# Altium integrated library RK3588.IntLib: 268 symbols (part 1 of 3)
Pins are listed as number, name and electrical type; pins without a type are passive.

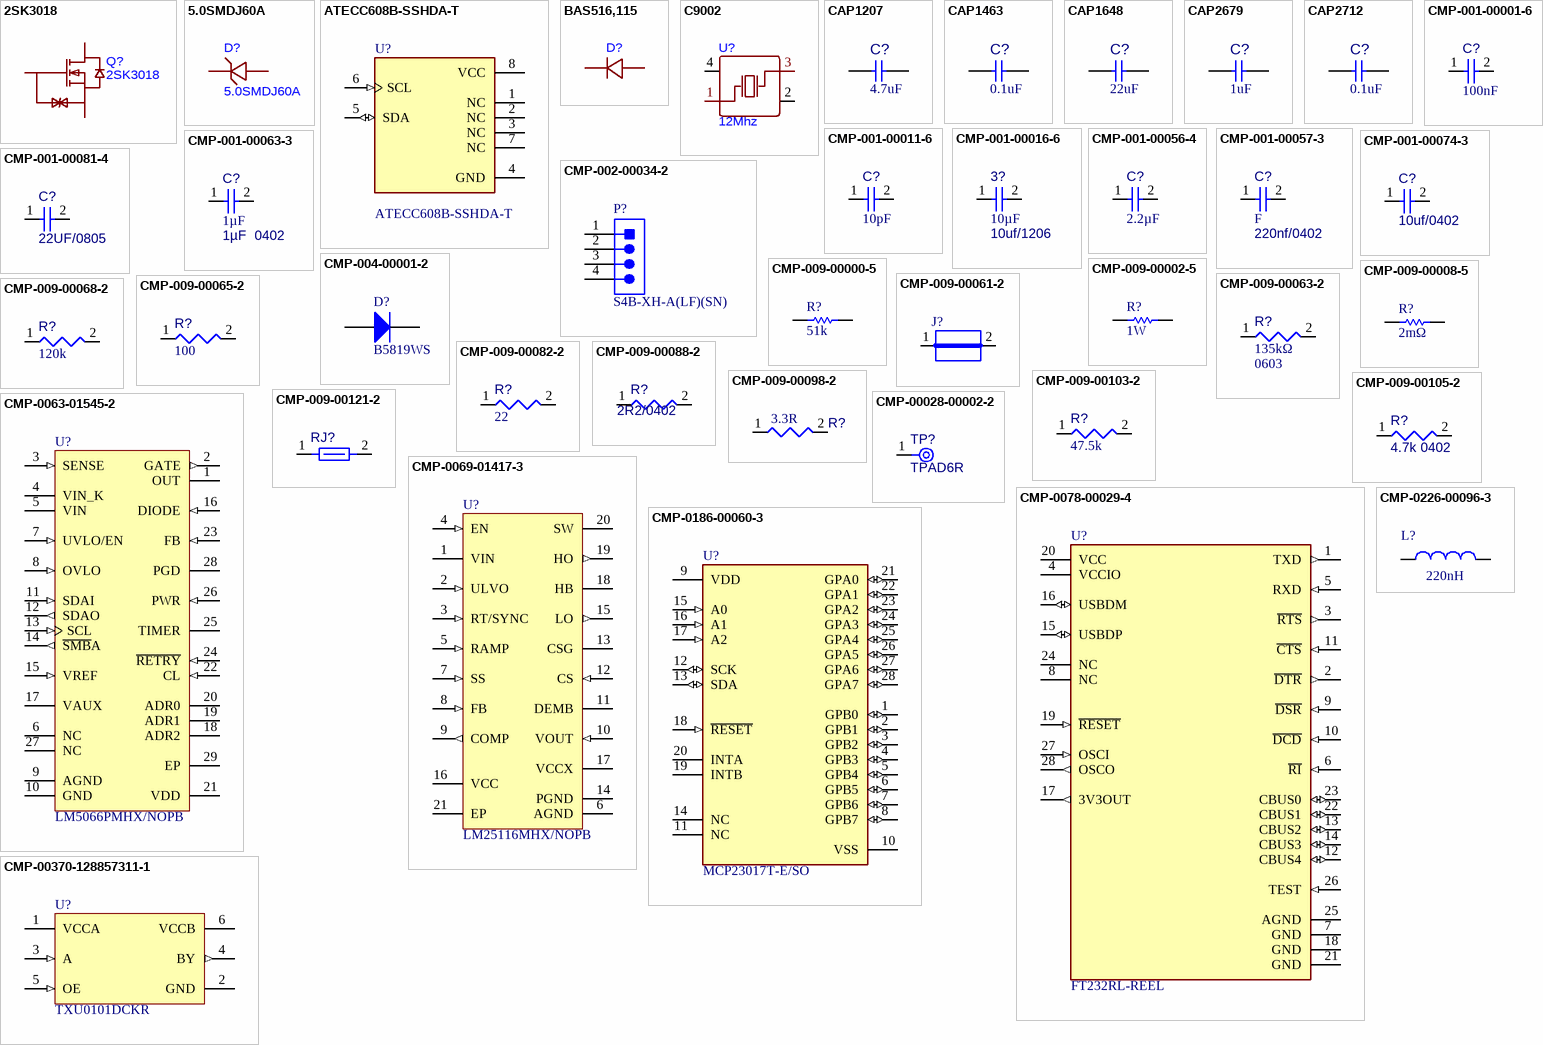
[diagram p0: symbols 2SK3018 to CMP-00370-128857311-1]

## 2SK3018
designator Q?
footprint SOT-23-3_L2.9-W1.3-P1.90-LS2.4-BR
pins: 1 G, 2 S, 3 D

## 5.0SMDJ60A
designator D?
footprint SMC_L6.9-W5.9-LS7.9-RD
pins: 1, 2

## ATECC608B-SSHDA-T
designator U?
Security ICs / Authentication ICs ECC/ECDH, I2C, SOIC T/R; MF: Microchip Technology
footprint SOIC127P600X175-8N
pins: 1 NC, 2 NC, 3 NC, 4 GND (power), 5 SDA (io), 6 SCL (in), 7 NC, 8 VCC (power)

## BAS516,115
designator D?
BAS516,115
footprint SOD-523F_L1.2-W0.8-LS1.7-RD
pins: 1 C, 2 A

## C9002
designator U?, comment 12Mhz
MN: ABM8-272-T3
footprint CRYSTAL-SMD_4P-L3.2-W2.5-BL
pins: 1 XTAL, 2 GND, 3 XTAL, 4 GND

## CAP1207
designator C?, comment value 4.7uF  (hidden comment: Capacitor NP)
Manufacturer 1: Murata; Manufacturer Part Number 1: GRM155R60J475ME47D; MCHP-ID: CAP1207; Voltage: 6.3V; Description_: CAP CER 4.7uF 6.3V 20% X5R SMD 0402; Dev Tools Status: Production; Tolerance: 20%; Temperature Coeffcient: X5R; Type: Ceramic; Populated: YES; Owner: Tad Ahlvers; Restricted Sourcing: No
footprint CAP_C_0402
pins: 1, 2
1 alternate drawing of the same symbol

## CAP1463
designator C?, comment value 0.1uF  (hidden comment: Capacitor NP)
Manufacturer 1: TDK Corporation; Manufacturer Part Number 1: C1005X7R1H104K050BB; MCHP-ID: CAP1463; Voltage: 50V; Description_: CAP CER 0.1uF 50V 10% X7R SMD 0402; Dev Tools Status: Production; Tolerance: 10%; Type: Ceramic; Owner: Jamus Griego; Populated: YES; Temperature Coefficient: X7R; Restricted Sourcing: No
footprint CAP_C_0402
pins: 1, 2
2 alternate drawings of the same symbol

## CAP1648
designator C?, comment value 22uF  (hidden comment: Capacitor NP)
Manufacturer 1: TDK Corporation; Manufacturer Part Number 1: C1608X5R1A226M080AC; MCHP-ID: CAP1648; Voltage: 10V; Description_: CAP CER 22uF 10V 20% X5R SMD 0603; Dev Tools Status: Production; Temperature Coefficient: X5R; Type: Ceramic; Populated: YES; Tolerance: 20%; Owner: Razvan Cristescu; Restricted Sourcing: No
footprint CAP_C_0603
pins: 1, 2
2 alternate drawings of the same symbol

## CAP2679
designator C?, comment value 1uF  (hidden comment: Capacitor NP)
Manufacturer 1: Murata; Manufacturer Part Number 1: GRM033R60J105MEA2D; MCHP-ID: CAP2679; Voltage: 6.3V; Description_: CAP CER 1uF 6.3V 20% X5R SMD 0201; Dev Tools Status: Design; Tolerance: 20%; Temperature Coefficient: X5R; Type: Ceramic; Owner: Balaji Narayana; Populated: YES; Restricted Sourcing: No
footprint CAP_C_0201
pins: 1, 2
2 alternate drawings of the same symbol

## CAP2712
designator C?, comment value 0.1uF  (hidden comment: Capacitor NP)
Manufacturer 1: Murata Electronics; Manufacturer Part Number 1: GRM033R61A104KE15D; MCHP-ID: CAP2712; Voltage: 10V; Description_: CAP CER 0.1uF 10V 10% 0201; Dev Tools Status: Design; Tolerance: 10%; Temperature Coefficient: X5R; Type: Ceramic; Owner: Balaji Narayana; Populated: YES; Restricted Sourcing: No
footprint CAP_C_0201
pins: 1, 2
2 alternate drawings of the same symbol

## CMP-001-00001-6
designator C?, comment value 100nF  (hidden comment: Capacitor 0.1 uF +/- 5% 16 V 0402)
Chip Capacitor, 0.1 uF, +/- 5%, 16 V, 0402 (1005 Metric); Manufacturer: Yageo Group; Manufacturer Part Number: C0402C104J4RACTU; Manufacturer: Murata; Manufacturer Part Number: GRM155R71C104JA88D; Capacitor Type: Ceramic; Voltage Rating: 16V
footprint CAPC1005X56X25LL10T15 (Chip Capacitor, 2-Leads, Body 1.10x0.60mm, IPC High Density)
footprint CAPC1005X56X25NL10T15 (Chip Capacitor, 2-Leads, Body 1.10x0.60mm, IPC Medium Density)
footprint CAPC1005X56X25ML10T15 (Chip Capacitor, 2-Leads, Body 1.10x0.60mm, IPC Low Density)
pins: 1, 2

## CMP-001-00011-6
designator C?, comment value 10pF  (hidden comment: Capacitor 10 pF +/- 0.25 pF 50 V 0402)
Chip Capacitor, 10 pF, +/- 0.25 pF, 50 V, 0402 (1005 Metric); Manufacturer: Yageo Group; Manufacturer Part Number: C0402C100C5GACTU; Manufacturer: KYOCERA AVX; Manufacturer Part Number: 04025A100JAT2A; Manufacturer: TDK; Manufacturer Part Number: C1005C0G1H100D050BA; Voltage Rating: 50V; Tolerance: 0.25%; Capacitor Type: Ceramic
footprint CAPC1005X55X30LL05T10 (Chip Capacitor, 2-Leads, Body 1.05x0.55mm, IPC High Density)
footprint CAPC1005X55X30ML05T10 (Chip Capacitor, 2-Leads, Body 1.05x0.55mm, IPC Low Density)
footprint CAPC1005X55X30NL05T10 (Chip Capacitor, 2-Leads, Body 1.05x0.55mm, IPC Medium Density)
pins: 1, 2

## CMP-001-00016-6
designator 3?, comment 10uf/1206  value 10µF
10uF 50V X5R ±10% 1206 Multilayer Ceramic Capacitors MLCC - SMD/SMT ROHS; Manufacturer: KYOCERA AVX; Manufacturer Part Number: 1206YC106KAT2A; Manufacturer: Yageo Group; Manufacturer Part Number: C1206C106K4RACTU; Voltage Rating: 50; MN: CL31A106KBHNNNE
footprint CAPC3216X180X50NL20T25 (Chip Capacitor, 2-Leads, Body 3.40x1.80mm, IPC Medium Density)
footprint CAPC3216X180X50LL20T25 (Chip Capacitor, 2-Leads, Body 3.40x1.80mm, IPC High Density)
footprint CAPC3216X180X50ML20T25 (Chip Capacitor, 2-Leads, Body 3.40x1.80mm, IPC Low Density)
pins: 1, 2

## CMP-001-00056-4
designator C?, comment value 2.2µF  (hidden comment: Capacitor 2,2µF +/-20% 10V 0402)
Chip Capacitor, 2,2µF +/-20%, 10V, 0402, Thickness 0.6 mm; Manufacturer: Samsung Electro-Mechanics; Manufacturer Part Number: CL05A225KP7NSB8; Manufacturer: Murata; Manufacturer Part Number: GRM155R61C225KE11D; Manufacturer: TDK; Manufacturer Part Number: C1005X5R1A225K; Manufacturer Part Number: GRM155R61A225KE95D; Manufacturer Part Number: GRM155R61C225KE44D; Manufacturer Part Number: GRT155R61E225KE13D; Tolerance: 10%
footprint CAPC0402(1005)60_L (Chip Capacitor, Body 1.0x0.5mm, Height 0.6mm, IPC High Density)
pins: 1, 2

## CMP-001-00057-3
designator C?, comment 220nf/0402  value F
Chip Capacitor, 220nF +/-20%, 10V, 0402, Thickness 0.6 mm; Manufacturer: TDK; Manufacturer Part Number: C1005X7R1A224K; Manufacturer Part Number: C1005X5R1A224K; Manufacturer: Yageo Group; Manufacturer Part Number: CC0402KRX5R6BB224; Tolerance: 10%; MN: CL05A224KA5NNNC
footprint CAPC0402(1005)60_L (Chip Capacitor, Body 1.0x0.5mm, Height 0.6mm, IPC High Density)
pins: 1, 2

## CMP-001-00063-3
designator C?, comment 1µF  0402  value 1µF
Chip Capacitor, 1µF +/-20%, 10V, 0402, Thickness 0.6 mm; Manufacturer: KYOCERA AVX; Manufacturer Part Number: 0402ZD105KAT2A; Manufacturer: Yageo Group; Manufacturer Part Number: C0402C105K8PACTU; Manufacturer Part Number: CC0402KRX5R6BB105; Manufacturer: TDK; Manufacturer Part Number: C1005X5R1A105K050BB; Manufacturer Part Number: C1005X6S1A105K; Manufacturer Part Number: C0402C105K8PAC; Tolerance: 10%; MN: CL05A105KP5NNNC
footprint CAPC0402(1005)60_L (Chip Capacitor, Body 1.0x0.5mm, Height 0.6mm, IPC High Density)
pins: 1, 2

## CMP-001-00074-3
designator C?, comment 10uf/0402
10uF 6.3V X5R ±20% 0402 Multilayer Ceramic Capacitors MLCC - SMD/SMT ROHS; Manufacturer: Murata; Manufacturer Part Number: GRM155R60J106ME15D; Value: 10µF; Tolerance: 10%; MN: GRM155R60J106ME44D
footprint CAPC0402(1005)60_L (Chip Capacitor, Body 1.0x0.5mm, Height 0.6mm, IPC High Density)
pins: 1, 2

## CMP-001-00081-4
designator C?, comment 22UF/0805
22uF 25V X5R ±20% 0805 Multilayer Ceramic Capacitors MLCC - SMD/SMT ROHS; Manufacturer: Murata; Manufacturer Part Number: GRM219R61C226ME15L; Manufacturer: Samsung Electro-Mechanics; Manufacturer Part Number: CL21A226MOCLRNC; Manufacturer: TDK; Manufacturer Part Number: C2012X5R1C226M; Manufacturer Part Number: CL21A226MOQNNNE; Manufacturer Part Number: CL21A226KOQNNNE; Manufacturer Part Number: GRM21BR61C226ME44L; Voltage Rating: 16V; Tolerance: 5%; MN: CL21A226MAQNNNE
footprint CAPC0805(2012)145_L (Chip Capacitor, Body 2.0x1.2mm, Height 1.45mm, IPC High Density)
pins: 1, 2

## CMP-002-00034-2
designator P?, comment S4B-XH-A(LF)(SN)
Male Header, Pitch 2.5 mm, 1 x 4 Position, Height 6.1 mm, Tail Length 3.4 mm, -25 to 85 degC, RoHS, Bulk; Manufacturer: JST
footprint JST-S4B-XH-A(LF)(SN)_V (Header, 4-Leads, Body 12.4x11.5mm, Pitch 2.5mm)
pins: 1, 2, 3, 4

## CMP-004-00001-2
designator D?, comment B5819WS
-55℃~+125℃ 1.5A 1A 40V 600mV@1A Independent SOD-323 Schottky Diodes ROHS; Manufacturer: Fairchild; Manufacturer: onsemi; Manufacturer Part Number: 1N4148WS; Recovery Time: 4ns; Forward Voltage: 1V; Peak Reverse Current: 5uA; Forward Current: 150mA; Capacitance: -323f
footprint FAIR-SOD-323_V (SODFL, 2-Leads, Body 1.25x1.7mm)
pins: 1 A, 2 K

## CMP-009-00000-5
designator R?, comment value 51k  (hidden comment: Resistor 51k +/-5% 0402 63 mW)
Chip Resistor, 51 KOhm, +/- 5%, 0.063 W, -55 to 155 degC, 0402 (1005 Metric); Manufacturer: Vishay; Manufacturer Part Number: CRCW040251K0JNED; Power: 63mW; MN: RC0402JR-0751KL
footprint RESC1005X40X25ML05T10 (Chip Resistor, 2-Leads, Body 1.05x0.55mm, IPC Low Density)
footprint RESC1005X40X25NL05T10 (Chip Resistor, 2-Leads, Body 1.05x0.55mm, IPC Medium Density)
footprint RESC1005X40X25LL05T10 (Chip Resistor, 2-Leads, Body 1.05x0.55mm, IPC High Density)
pins: 1, 2

## CMP-009-00002-5
designator R?, comment value 1W  (hidden comment: HoYH1206-1W-10mR-1%)
10mΩ 1W Current Sense Resistor SMD ±1% ±100ppm/℃ 1206 Current Sense Resistors / Shunt Resistors ROHS; Manufacturer: Yageo Group; Manufacturer Part Number: RC1206JR-070RL; Manufacturer: Vishay; Manufacturer Part Number: CRCW12060000Z0EA; Tolerance: 5%; Voltage Rating: 200V
footprint RESC3216X60X45ML15T20 (Chip Resistor, 2-Leads, Body 3.3x1.75mm, IPC Low Density)
footprint RESC3216X60X45NL15T20 (Chip Resistor, 2-Leads, Body 3.3x1.75mm, IPC Medium Density)
footprint RESC3216X60X45LL15T20 (Chip Resistor, 2-Leads, Body 3.3x1.75mm, IPC High Density)
pins: 1, 2

## CMP-009-00008-5
designator R?, comment value 2mΩ  (hidden comment: CSNL1206FT2L00)
1W 2mΩ Current Sense Resistor ±1% ±50ppm/℃ 1206 Current Sense Resistors / Shunt Resistors ROHS; Manufacturer: Panasonic; Manufacturer Part Number: ERJ-8GEY0R00V; Tolerance: 0.05%; Voltage Rating: 200V
footprint RESC3116X70X50ML13T20 (Chip Resistor, 2-Leads, Body 3.25x1.65mm, IPC Low Density)
footprint RESC3116X70X50NL13T20 (Chip Resistor, 2-Leads, Body 3.25x1.65mm, IPC Medium Density)
footprint RESC3116X70X50LL13T20 (Chip Resistor, 2-Leads, Body 3.25x1.65mm, IPC High Density)
pins: 1, 2

## CMP-009-00061-2
designator J?, comment JUMPER  (value not drawn)
footprint JUMPER
pins: 1, 2

## CMP-009-00063-2
designator R?, comment value 135kΩ  Case/Package: 0603  (hidden comment: RT0603BRD07135KL)
-55℃~+155℃ 100mW 135kΩ 75V Thin Film Resistor ±0.1% ±25ppm/℃ 0603 Chip Resistor - Surface Mount ROHS
footprint RESC0603(1608)_L (Chip Resistor, Body 1.6x0.8mm, IPC High Density)
pins: 1, 2
1 alternate drawing of the same symbol

## CMP-009-00065-2
designator R?, comment value 100  (hidden comment: 100R / 0402)
100R 0.063W 1% 0402 (1005 Metric)  SMD; Power: 63mW; MN: 0402WGF1000TCE
footprint RESC0402(1005)_L (Chip Resistor, Body 1.0x0.5mm, IPC High Density)
pins: 1, 2
1 alternate drawing of the same symbol

## CMP-009-00068-2
designator R?, comment value 120k  (hidden comment: 120k/0402)
120K 0.063W 1% 0402 (1005 Metric)  SMD; Power: 63mW; MN: 0402WGF1203TCE
footprint RESC0402(1005)_L (Chip Resistor, Body 1.0x0.5mm, IPC High Density)
pins: 1, 2
1 alternate drawing of the same symbol

## CMP-009-00082-2
designator R?, comment value 22  (hidden comment: 22R2J)
22R 0.063W 5% 0402 (1005 Metric)  SMD; Power: 63mW; MN: 0402WGF220JTCE
footprint RESC0402(1005)_L (Chip Resistor, Body 1.0x0.5mm, IPC High Density)
pins: 1, 2
1 alternate drawing of the same symbol

## CMP-009-00088-2
designator R?, comment 2R2/0402
2R2 0.063W 5% 0402 (1005 Metric)  SMD; Power: 63mW; MN: CR0402JF02R2G
footprint RESC0402(1005)_L (Chip Resistor, Body 1.0x0.5mm, IPC High Density)
pins: 1, 2
1 alternate drawing of the same symbol

## CMP-009-00098-2
designator R?, comment value 3.3R  (hidden comment: 3D3R2J)
3R3 0.063W 5% 0402 (1005 Metric)  SMD; Power: 63mW; MN: 0402WGJ033JTCE
footprint RESC0402(1005)_L (Chip Resistor, Body 1.0x0.5mm, IPC High Density)
pins: 1, 2
1 alternate drawing of the same symbol

## CMP-009-00103-2
designator R?, comment value 47.5k  (hidden comment: 47D5KR2F)
47K5 0.063W 1% 0402 (1005 Metric)  SMD; Power: 63mW
footprint RESC0402(1005)_L (Chip Resistor, Body 1.0x0.5mm, IPC High Density)
pins: 1, 2
1 alternate drawing of the same symbol

## CMP-009-00105-2
designator R?, comment 4.7k 0402
4K7 0.063W 1% 0402 (1005 Metric)  SMD; Power: 63mW; MN: 0402WGF4701TCE
footprint RESC0402(1005)_L (Chip Resistor, Body 1.0x0.5mm, IPC High Density)
pins: 1, 2
1 alternate drawing of the same symbol

## CMP-009-00121-2
designator RJ?, comment Net Tie 12x8mil  (value not drawn)  (net tie, no BOM)
footprint SHORT06-FP
pins: 1, 2

## CMP-00028-00002-2
designator TP?, comment TPAD6R  (no BOM)
0.6mm round
footprint TP06R (Testpoint, round, d=0.6mm)
pins: 1 TP

## CMP-0063-01545-2
designator U?, comment LM5066PMHX/NOPB
High Voltage System Power Management and Protection IC with PMBus, 28-pin TSSOP-EP, 2500 Reel; Manufacturer: Texas Instruments; CompType: MiscPower; PackageTopMarking: NSUZXYTTE#*LM5066PMH; PowerWise: Y
footprint PWP0028A_L (SOP, 28-leads, Body 4.5x9.8mm, Pitch 0.65mm, Thermal Pad 3x5.5mm, IPC High Density)
footprint PWP0028A_M (SOP, 28-leads, Body 4.5x9.8mm, Pitch 0.65mm, Thermal Pad 3x5.5mm, IPC Low Density)
footprint PWP0028A_N (SOP, 28-leads, Body 4.5x9.8mm, Pitch 0.65mm, Thermal Pad 3x5.5mm, IPC Medium Density)
pins: 1 OUT (power), 2 GATE (out), 3 SENSE (in), 4 VIN_K (power), 5 VIN (power), 6 NC, 7 UVLO/EN (in), 8 OVLO (in), 9 AGND (power), 10 GND (power), 11 SDAI (in), 12 SDAO (out), 13 SCL (in), 14 ~{SMB}A (out), 15 VREF (in), 16 DIODE (in), 17 VAUX (power), 18 ADR2, 19 ADR1, 20 ADR0, 21 VDD (power), 22 CL (in), 23 FB (in), 24 ~{RETRY} (in), 25 TIMER, 26 PWR (in), 27 NC, 28 PGD (hiz), 29 EP (power)

## CMP-0069-01417-3
designator U?, comment LM25116MHX/NOPB
Wide Range Synchronous Buck Controller, 20-pin TSSOP-EP, Pb-Free; Manufacturer: Texas Instruments; CompType: Switcher; PowerWise: Y; PackageTopMarking: NSUZXYTT*LM25116*MH
footprint PWP0020A_N (SOP, 20-Leads, Body 6.6x4.5mm, Pitch 0.65mm, Thermal Pad 4.2x3mm, IPC Medium Density)
footprint PWP0020A_M (SOP, 20-Leads, Body 6.6x4.5mm, Pitch 0.65mm, Thermal Pad 4.2x3mm, IPC Low Density)
footprint PWP0020A_L (SOP, 20-Leads, Body 6.6x4.5mm, Pitch 0.65mm, Thermal Pad 4.2x3mm, IPC High Density)
pins: 1 VIN (power), 2 ULVO (in), 3 RT/SYNC (in), 4 EN (in), 5 RAMP (in), 6 AGND (power), 7 SS (in), 8 FB (in), 9 COMP (out), 10 VOUT (in), 11 DEMB, 12 CS (in), 13 CSG, 14 PGND (power), 15 LO (out), 16 VCC (power), 17 VCCX (power), 18 HB, 19 HO (out), 20 SW (power), 21 EP (power)

## CMP-0078-00029-4
designator U?, comment FT232RL-REEL
IC USB FS SERIAL UART 28-SSOP; Data Rate: 12Mbps; Max Supply Voltage: 5.25V; Operating Supply Current: 15mA; Number of Channels: 1; Voltage: 5V; Min Supply Voltage: 3.3V
footprint FP-SSOP-28-MFG
footprint FP-SSOP-28-IPC_C
footprint FP-SSOP-28-IPC_B
footprint FP-SSOP-28-IPC_A
pins: 1 TXD (out), 2 ~{DTR} (out), 3 ~{RTS} (out), 4 VCCIO (power), 5 RXD (in), 6 ~{RI} (in), 7 GND (power), 8 NC, 9 ~{DSR} (in), 10 ~{DCD} (in), 11 ~{CTS} (in), 12 CBUS4 (io), 13 CBUS2 (io), 14 CBUS3 (io), 15 USBDP (io), 16 USBDM (io), 17 3V3OUT (out), 18 GND (power), 19 ~{RESET} (in), 20 VCC (power), 21 GND (power), 22 CBUS1 (io), 23 CBUS0 (io), 24 NC, 25 AGND (power), 26 TEST (in), 27 OSCI (in), 28 OSCO (out)

## CMP-0186-00060-3
designator U?, comment MCP23017T-E/SO
IC I/O EXPANDER I2C 16B 28SOIC; Number of Channels: 1; Operating Supply Voltage: 5.5V; Max Frequency: 1.7MHz; Nominal Supply Current: 1mA; Number of Bits: 16
footprint FP-C04-052-MFG
footprint FP-C04-052-IPC_C
footprint FP-C04-052-IPC_A
footprint FP-C04-052-IPC_B
pins: 1 GPB0 (io), 2 GPB1 (io), 3 GPB2 (io), 4 GPB3 (io), 5 GPB4 (io), 6 GPB5 (io), 7 GPB6 (io), 8 GPB7 (io), 9 VDD (power), 10 VSS (power), 11 NC, 12 SCK (io), 13 SDA (io), 14 NC, 15 A0 (in), 16 A1 (in), 17 A2 (in), 18 ~{RESET} (in), 19 INTB (oc), 20 INTA (oc), 21 GPA0 (io), 22 GPA1 (io), 23 GPA2 (io), 24 GPA3 (io), 25 GPA4 (io), 26 GPA5 (io), 27 GPA6 (io), 28 GPA7 (io)

## CMP-0226-00096-3
designator L?, comment 220nH
INDUCTOR, 0.22UH, 27A, 20%; Product Range: WURTH ELEKTRONIK - WE-HCC Series; Indu; Core Material: Ferrite; Self Resonant Frequency: 280MHz; Test Frequency: 100kHz; Series Resistance: 530µΩ; Shielding: Shielded; Saturation Current: 82.9A; DC Resistance (DCR): 1.1mΩ
footprint WE-HCC_1210
pins: 1, 2

## CMP-00370-128857311-1
designator U?, comment TXU0101DCKR
Single channel fixed-direction level shifter 6-SC70 -40 to 125; Manufacturer Lifecycle Status: ACTIVE; Number of Inputs: 1; Propagation Delay: 69ns; Max Junction Temperature (Tj): 150°C; Data Rate: 200Mbps; Nominal Supply Current: 2.5µA
footprint FP-DCK0006A-MFG
footprint FP-DCK0006A-IPC_A
footprint FP-DCK0006A-IPC_B
footprint FP-DCK0006A-IPC_C
pins: 1 VCCA (power), 2 GND (power), 3 A (in), 4 BY (out), 5 OE (in), 6 VCCB (power)

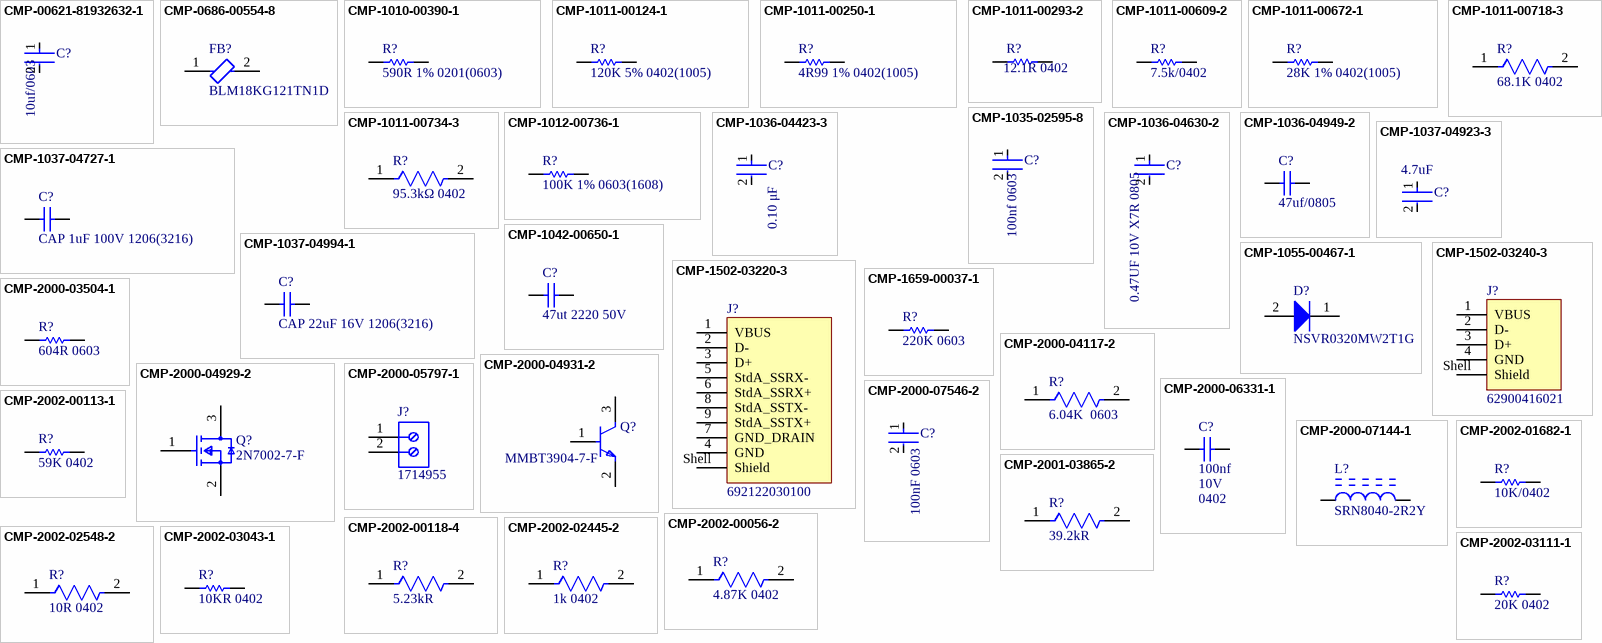
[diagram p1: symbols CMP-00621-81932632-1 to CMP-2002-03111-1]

## CMP-00621-81932632-1
designator C?, comment 10uf/0603
CC0603KRX5R7BB106 Multilayer Ceramic Capacitor, 10 uF, 16 V, ± 10%, X5R, 0603 [1608 Metric]; NexarPartId: 81932632; Capacitance: 10µF; Voltage Rating: 16V
footprint FP-CC0603-DC-MFG (Multilayer Ceramic Capacitor, 10 uF, 16 V, ± 10%, X5R, 0603 [1608 Metric])
footprint FP-CC0603-DC-IPC_A (Multilayer Ceramic Capacitor, 10 uF, 16 V, ± 10%, X5R, 0603 [1608 Metric])
footprint FP-CC0603-DC-IPC_B (Multilayer Ceramic Capacitor, 10 uF, 16 V, ± 10%, X5R, 0603 [1608 Metric])
footprint FP-CC0603-DC-IPC_C (Multilayer Ceramic Capacitor, 10 uF, 16 V, ± 10%, X5R, 0603 [1608 Metric])
pins: 1, 2

## CMP-0686-00554-8
designator FB?, comment BLM18KG121TN1D
FERRITE BEAD 120 OHM 0603 1LN; Max Current Rating: 3A; DC Resistance (DCR): 30mR; Impedance: 120R; Number of Lines: 1; Test Frequency: 100MHz; Tolerance: 25%
footprint FP-BLM18-0_15-t0_6-d1_2-IPC_A
footprint FP-BLM18-0_15-t0_6-d1_2-IPC_B
footprint FP-BLM18-0_15-t0_6-d1_2-IPC_C
footprint FP-BLM18-0_15-t0_6-d1_2-MFG
pins: 1, 2

## CMP-1010-00390-1
designator R?, comment 590R 1% 0201(0603)
590R 0.05W 1% 0201 (0603 Metric)  SMD; Case-Metric: 0603; Case-EIA: 0201; Value: 590.00 Ohm; MN: RC-01W5900FT
footprint RESC0201(0603)_L (Chip Resistor, Body 0.6x0.3mm, IPC High Density)
footprint RESC0201(0603)_M (Chip Resistor, Body 0.6x0.3mm, IPC Low Density)
footprint RESC0201(0603)_N (Chip Resistor, Body 0.6x0.3mm, IPC Medium Density)
pins: 1, 2
1 alternate drawing of the same symbol

## CMP-1011-00124-1
designator R?, comment 120K 5% 0402(1005)
120K 0.063W 5% 0402 (1005 Metric)  SMD; Value: 120000.00 Ohm; Case-EIA: 0402; Case-Metric: 1005
footprint RESC0402(1005)_M (Chip Resistor, Body 1.0x0.5mm, IPC Low Density)
footprint RESC0402(1005)_N (Chip Resistor, Body 1.0x0.5mm, IPC Medium Density)
footprint RESC0402(1005)_L (Chip Resistor, Body 1.0x0.5mm, IPC High Density)
pins: 1, 2
1 alternate drawing of the same symbol

## CMP-1011-00250-1
designator R?, comment 4R99 1% 0402(1005)
4R99 0.063W 1% 0402 (1005 Metric)  SMD; Case-Metric: 1005; Value: 4.99 Ohm; Case-EIA: 0402
footprint RESC0402(1005)_L (Chip Resistor, Body 1.0x0.5mm, IPC High Density)
footprint RESC0402(1005)_N (Chip Resistor, Body 1.0x0.5mm, IPC Medium Density)
footprint RESC0402(1005)_M (Chip Resistor, Body 1.0x0.5mm, IPC Low Density)
pins: 1, 2
1 alternate drawing of the same symbol

## CMP-1011-00293-2
designator R?, comment 12.1R 0402
Part Number: RC0402FR-0712R1L; Manufacturer: Yageo / Phycomp
footprint RESC1005X40X25LL05T10 (Chip Resistor, 2-Leads, Body 1.00x0.50mm, IPC High Density)
footprint RESC1005X40X25NL05T10 (Chip Resistor, 2-Leads, Body 1.00x0.50mm, IPC Medium Density)
footprint RESC1005X40X25ML05T10 (Chip Resistor, 2-Leads, Body 1.00x0.50mm, IPC Low Density)
pins: 1, 2
1 alternate drawing of the same symbol

## CMP-1011-00609-2
designator R?, comment 7.5k/0402
Part Number: RC0402FR-077K5L; Manufacturer: Yageo / Phycomp
footprint RESC1005X40X25LL05T10 (Chip Resistor, 2-Leads, Body 1.00x0.50mm, IPC High Density)
footprint RESC1005X40X25NL05T10 (Chip Resistor, 2-Leads, Body 1.00x0.50mm, IPC Medium Density)
footprint RESC1005X40X25ML05T10 (Chip Resistor, 2-Leads, Body 1.00x0.50mm, IPC Low Density)
pins: 1, 2
1 alternate drawing of the same symbol

## CMP-1011-00672-1
designator R?, comment 28K 1% 0402(1005)
28K 0.063W 1% 0402 (1005 Metric)  SMD; Case-Metric: 1005; Value: 28000.00 Ohm; Case-EIA: 0402
footprint RESC0402(1005)_L (Chip Resistor, Body 1.0x0.5mm, IPC High Density)
footprint RESC0402(1005)_M (Chip Resistor, Body 1.0x0.5mm, IPC Low Density)
footprint RESC0402(1005)_N (Chip Resistor, Body 1.0x0.5mm, IPC Medium Density)
pins: 1, 2
1 alternate drawing of the same symbol

## CMP-1011-00718-3
designator R?, comment 68.1K 0402
RES Thick Film, 68.1kΩ, 1%, 0.063W, 100ppm/°C, 0402; Voltage Rating (DC): 50V; Max Power Dissipation: 63mW; Resistance: 68.1kR
footprint FP-CRCW0402-e3-IPC_B
footprint FP-CRCW0402-e3-IPC_C
footprint FP-CRCW0402-e3-IPC_A
footprint FP-CRCW0402-e3-MFG
pins: 1, 2

## CMP-1011-00734-3
designator R?, comment 95.3kΩ 0402
RES Thick Film, 95.3kΩ, 1%, 0.063W, 100ppm/°C, 0402 / CRCW040295K3FKED; Power Rating: 63mW; Voltage Rating (DC): 50V; Resistance: 95.3kR
footprint FP-CRCW0402-e3-IPC_A
footprint FP-CRCW0402-e3-IPC_C
footprint FP-CRCW0402-e3-MFG
footprint FP-CRCW0402-e3-IPC_B
pins: 1, 2

## CMP-1012-00736-1
designator R?, comment 100K 1% 0603(1608)
100K 0.1W 1% 0603 (1608 Metric)  SMD; Value: 100000.00 Ohm; Case-Metric: 1608; Case-EIA: 0603
footprint RESC0603(1608)_N (Chip Resistor, Body 1.6x0.8mm, IPC Medium Density)
footprint RESC0603(1608)_M (Chip Resistor, Body 1.6x0.8mm, IPC Low Density)
footprint RESC0603(1608)_L (Chip Resistor, Body 1.6x0.8mm, IPC High Density)
pins: 1, 2
1 alternate drawing of the same symbol

## CMP-1035-02595-8
designator C?, comment 100nf 0603
Chip Multilayer Ceramic Capacitors for General Purpose, 0603, 0.10uF, X7R, 15%, 10%, 100V
footprint FP-GRM188-0_1-e0_2_0_5-IPC_B
footprint FP-GRM188-0_1-e0_2_0_5-IPC_A
footprint FP-GRM188-0_1-e0_2_0_5-MFG
footprint FP-GRM188-0_1-e0_2_0_5-IPC_C
pins: 1, 2

## CMP-1036-04423-3
designator C?, comment value 0.10 μF  (hidden comment: C0805C104M5RACTU)
CAP CER 0.1UF 50V X7R 0805; Manufacturer: KEMET; Tolerance: 0.2; Temperature Coefficient: 30ppm/°C; Material: Ceramic
footprint FP-C0805C-DN-MFG
footprint FP-C0805C-DN-IPC_C
footprint FP-C0805C-DN-IPC_B
footprint FP-C0805C-DN-IPC_A
pins: 1, 2

## CMP-1036-04630-2
designator C?, comment 0.47UF 10V X7R 0805
CAP CER 0.47UF 10V X7R 0805 / C0805C474J8RACTU; Manufacturer: KEMET; Value: 0.47 μF; Temperature Coefficient: 30ppm/°C; Tolerance: 0.05; Material: Ceramic
footprint FP-C0805C-DN-MFG
footprint FP-C0805C-DN-IPC_C
footprint FP-C0805C-DN-IPC_B
footprint FP-C0805C-DN-IPC_A
pins: 1, 2

## CMP-1036-04949-2
designator C?, comment 47uf/0805
Manufacturer: Kemet; Part Number: C0805C476M7PACTU
footprint CAPC2013X145X50ML20T25 (Chip Capacitor, 2-Leads, Body 2.00x1.25mm, IPC Low Density)
footprint CAPC2013X145X50NL20T25 (Chip Capacitor, 2-Leads, Body 2.00x1.25mm, IPC Medium Density)
footprint CAPC2013X145X50LL20T25 (Chip Capacitor, 2-Leads, Body 2.00x1.25mm, IPC High Density)
pins: 1, 2
1 alternate drawing of the same symbol

## CMP-1037-04727-1
designator C?, comment CAP 1uF 100V 1206(3216)
CAP 1uF 100V ±5% 1206 (3216 Metric) Thickness 1.9mm SMD; Case-EIA: 1206; Tolerance: Â±5%; Case-Metric: 3216
footprint CAPC1206(3216)190_M (Chip Capacitor, Body 3.2x1.6mm, Height 1.9mm, IPC Low Density)
footprint CAPC1206(3216)190_N (Chip Capacitor, Body 3.2x1.6mm, Height 1.9mm, IPC Medium Density)
footprint CAPC1206(3216)190_L (Chip Capacitor, Body 3.2x1.6mm, Height 1.9mm, IPC High Density)
pins: 1, 2
1 alternate drawing of the same symbol

## CMP-1037-04923-3
designator C?, comment Capacitance: 4.7uF  (hidden comment: GRM31CR71H475KA12L)
Chip Multilayer Ceramic Capacitors for General Purpose, 1206, 4.7uF, X7R, 15%, 10%, 50V
footprint FP-GRM31C-0_2-e0_3_0_8-IPC_C
footprint FP-GRM31C-0_2-e0_3_0_8-IPC_B
footprint FP-GRM31C-0_2-e0_3_0_8-IPC_A
footprint FP-GRM31C-0_2-e0_3_0_8-MFG
pins: 1, 2

## CMP-1037-04994-1
designator C?, comment CAP 22uF 16V 1206(3216)
CAP 22uF 16V -20% to +80% 1206 (3216 Metric) Thickness 1.9mm SMD; Case-Metric: 3216; Case-EIA: 1206
footprint CAPC1206(3216)190_L (Chip Capacitor, Body 3.2x1.6mm, Height 1.9mm, IPC High Density)
footprint CAPC1206(3216)190_N (Chip Capacitor, Body 3.2x1.6mm, Height 1.9mm, IPC Medium Density)
footprint CAPC1206(3216)190_M (Chip Capacitor, Body 3.2x1.6mm, Height 1.9mm, IPC Low Density)
pins: 1, 2
1 alternate drawing of the same symbol

## CMP-1042-00650-1
designator C?, comment 47ut 2220 50V
CAP 470nF 200V ±10% 2220 (5750 Metric) Thickness 2.2mm SMD; MN: CKG57NX7R1H476MT009W; Tolerance: 20%; Case-EIA: 2220
footprint CAPC2220(5750)230_N (Chip Capacitor, Body 5.7x5.0mm, Height 2.3mm, IPC Medium Density)
footprint CAPC2220(5750)230_M (Chip Capacitor, Body 5.7x5.0mm, Height 2.3mm, IPC Low Density)
footprint CAPC2220(5750)230_L (Chip Capacitor, Body 5.7x5.0mm, Height 2.3mm, IPC High Density)
pins: 1, 2
1 alternate drawing of the same symbol

## CMP-1055-00467-1
designator D?, comment NSVR0320MW2T1G
Schottky Barrier Diode, 2-Pin SOD-323, Pb-Free, Tape and Reel; Manufacturer: On Semiconductor; IFSM Max (A): 5; Configuration: Single
footprint ONSC-SOD-323-2-477-02_V (SOD, 2-Leads, Body 1.7x1.25mm)
pins: 1 K, 2 A

## CMP-1502-03220-3
designator J?, comment 692122030100
Conn USB 3.0 Type A RCP 9 POS 1.25mm Solder RA SMD 9 Terminal 1 Port T/R; Current Rating: 250mA; Insulation Resistance: 100MΩ; Number of Contacts: 9; Number of Ports: 1; Voltage Rating (AC): 30V; USB Standard: USB 3.0; Gender: Receptacle; Contact Resistance: 50mΩ
footprint 692122030100
pins: 1 VBUS, 2 D-, 3 D+, 4 GND, 5 StdA_SSRX-, 6 StdA_SSRX+, 7 GND_DRAIN, 8 StdA_SSTX-, 9 StdA_SSTX+, Shell Shield

## CMP-1502-03240-3
designator J?, comment 62900416021
Wr-com; Right Angle Version 2.0; Connector SMT Socket, 30 V AC, 1.5A, 62900; Operating Supply Voltage: 30V; Contact Resistance: 20mΩ; Insulation Resistance: 1GΩ; Connector Type: USB; Number of Contacts: 4; Gender: Receptacle; USB Standard: USB 2.0
footprint 62900416021
pins: 1 VBUS, 2 D-, 3 D+, 4 GND, Shell Shield

## CMP-1659-00037-1
designator R?, comment 220K 0603
Chip Resistor, 220 KOhm, +/- 1%, 100 mW, -55 to 155 degC, 0603 (1608 Metric), RoHS, Tape and Reel; Resistance: 0.1 Ohm; MN: RC0603FR-07220KL
footprint RESC1608X55X25ML10T15 (Chip Resistor, 2-Leads, Body 1.70x0.90mm, IPC Low Density)
footprint RESC1608X55X25LL10T15 (Chip Resistor, 2-Leads, Body 1.70x0.90mm, IPC High Density)
footprint RESC1608X55X25NL10T15 (Chip Resistor, 2-Leads, Body 1.70x0.90mm, IPC Medium Density)
pins: 1, 2

## CMP-2000-03504-1
designator R?, comment 604R 0603
CRCW0603604RFKEA / Resistance = 604 Ω / Tolerance = 1.0% / Power = 100 mW; Manufacturer: Vishay Dale
footprint RESC1609X50X30ML10T20 (Chip Resistor, 2-Leads, Body 1.55x0.85mm, IPC Low Density)
footprint RESC1609X50X30NL10T20 (Chip Resistor, 2-Leads, Body 1.55x0.85mm, IPC Medium Density)
footprint RESC1609X50X30LL10T20 (Chip Resistor, 2-Leads, Body 1.55x0.85mm, IPC High Density)
pins: 1, 2
1 alternate drawing of the same symbol

## CMP-2000-04117-2
designator R?, comment 6.04K  0603
RES 6.04K OHM 1% 1/10W 0603 / RC0603FR-076K04L; Temperature Coefficient: 100ppm/°C; Voltage Rating: 50V; Power Rating: 100mW; Resistance: 6.04kR
footprint FP-RC0603-0_55-IPC_A
footprint FP-RC0603-0_55-IPC_C
footprint FP-RC0603-0_55-IPC_B
footprint FP-RC0603-0_55-MFG
pins: 1, 2

## CMP-2000-04929-2
designator Q?, comment 2N7002-7-F
MOSFET N-CH 60V 115MA SOT23-3; Turn-On Delay Time: 7ns; Turn-Off Delay Time: 11ns; Drain to Source Resistance: 7.5R; Rise Time: 3ns; Drain to Source Breakdown Voltage: 70V; Input Capacitance: 50pF; Number of Elements: 1; Power Dissipation: 540mW; Max Power Dissipation: 300mW; Fall Time: 5.6ns; Gate to Source Voltage (Vgs): 20V; Threshold Voltage: 2.5V; Element Configuration: Single
footprint FP-SOT23-MFG
footprint FP-SOT23-IPC_B
footprint FP-SOT23-IPC_A
footprint FP-SOT23-IPC_C
pins: 1 G, 2 S, 3 D

## CMP-2000-04931-2
designator Q?, comment MMBT3904-7-F
TRANS NPN 40V 0.2A SMD SOT23-3; Frequency: 300MHz; Power Dissipation: 350mW; Element Configuration: Single; Max Power Dissipation: 300mW; Max Collector Current: 200mA; Collector Emitter Saturation Voltage: 300mV; Number of Elements: 1; hFE Min: 100; Collector Base Voltage (VCBO): 60V; Emitter Base Voltage (VEBO): 6V
footprint FP-SOT23-IPC_A
footprint FP-SOT23-MFG
footprint FP-SOT23-IPC_C
footprint FP-SOT23-IPC_B
pins: 1 B, 2 E, 3 C

## CMP-2000-05797-1
designator J?, comment 1714955
PC Terminal Block, Pitch 6.35 mm, 1 x 2 Position, Height 21.5 mm, Tail Lenght 5.1 mm, RoHS, Bulk; Manufacturer: Phoenix Contact
footprint PHOE-1714955_V (Terminal Block, 2-Leads, Body 12.7x12.5mm, Pitch 6.35mm)
pins: 1, 2

## CMP-2000-06331-1
designator C?, comment 100nf  Rated Voltage: 10V  Package Reference: 0402
Chip Capacitor, 0.1 uF, +/- 10%, 10 V, -55 to 125 degC, 0402 (1005 Metric), RoHS, Tape and Reel; Manufacturer: Murata; Capacitance: 100000pF; Dielectric: X7R
footprint CAPC1005X55X25LL05T10 (Chip Capacitor, 2-Leads, Body 1.05x0.55mm, IPC High Density)
footprint CAPC1005X55X25ML05T10 (Chip Capacitor, 2-Leads, Body 1.05x0.55mm, IPC Low Density)
footprint CAPC1005X55X25NL05T10 (Chip Capacitor, 2-Leads, Body 1.05x0.55mm, IPC Medium Density)
pins: 1, 2

## CMP-2000-07144-1
designator L?, comment SRN8040-2R2Y
Semi-Shielded Power Inductor, 2.2 uH, +/- 30%, 6.3 A, -40 to 125 degC, 2-Pin SMD, RoHS, Tape and Reel; Manufacturer: Bourns; Brand/Series: SRN8040Series; Current, Rating: 6.3A; Inductance: 2.2μH
footprint BOUR-SRN8040_V (SMD, 2-Leads, Body 8x8mm)
pins: 1, 2

## CMP-2000-07546-2
designator C?, comment 100nF 0603
Cap Ceramic 100nF 50V X7R 10% Pad SMD 0603 +125°C Automotive T/R / CGA3E2X7R1H104K080AA
footprint FP-CGA3E-0_3-0_1-IPC_A
footprint FP-CGA3E-0_3-0_1-IPC_C
footprint FP-CGA3E-0_3-0_1-IPC_B
footprint FP-CGA3E-0_3-0_1-MFG
pins: 1, 2

## CMP-2001-03865-2
designator R?, comment Resistance: 39.2kR  (hidden comment: CRCW080539K2FKEA)
RES Thick Film, 39.2kΩ, 1%, 0.125W, 100ppm/°C, 0805; Max Power Dissipation: 125mW; Voltage Rating (DC): 150V
footprint FP-CRCW0805-e3-IPC_C
footprint FP-CRCW0805-e3-IPC_B
footprint FP-CRCW0805-e3-IPC_A
footprint FP-CRCW0805-e3-MFG
pins: 1, 2

## CMP-2002-00056-2
designator R?, comment 4.87K 0402
RES Thick Film, 4.87kΩ, 1%, 0.063W, 100ppm/°C, 0402 / CRCW04024K87FKED; Voltage Rating: 50V; Resistance: 4.87kR; Max Power Dissipation: 63mW
footprint FP-CRCW0402-e3-IPC_C
footprint FP-CRCW0402-e3-MFG
footprint FP-CRCW0402-e3-IPC_B
footprint FP-CRCW0402-e3-IPC_A
pins: 1, 2

## CMP-2002-00113-1
designator R?, comment 59K 0402
CRCW040259K0FKED; Manufacturer: Vishay Dale
footprint RESC1005X40X25LL05T05 (Chip Resistor, 2-Leads, Body 1.00x0.50mm, IPC High Density)
footprint RESC1005X40X25NL05T05 (Chip Resistor, 2-Leads, Body 1.00x0.50mm, IPC Medium Density)
footprint RESC1005X40X25ML05T05 (Chip Resistor, 2-Leads, Body 1.00x0.50mm, IPC Low Density)
pins: 1, 2
1 alternate drawing of the same symbol

## CMP-2002-00118-4
designator R?, comment Resistance: 5.23kR  (hidden comment: CRCW04025K23FKED)
RES Thick Film, 5.23kΩ, 1%, 0.063W, 100ppm/°C, 0402; Max Power Dissipation: 63mW; Working Voltage: 50V
footprint FP-CRCW0402-e3-IPC_C
footprint FP-CRCW0402-e3-IPC_B
footprint FP-CRCW0402-e3-MFG
footprint FP-CRCW0402-e3-IPC_A
pins: 1, 2

## CMP-2002-01682-1
designator R?, comment 10K/0402
Manufacturer: Vishay BCcomponents; Part Number: TNPW040210K0DEED
footprint RESC1005X40X20NL05T10 (Chip Resistor, 2-Leads, Body 1.00x0.50mm, IPC Medium Density)
footprint RESC1005X40X20LL05T10 (Chip Resistor, 2-Leads, Body 1.00x0.50mm, IPC High Density)
footprint RESC1005X40X20ML05T10 (Chip Resistor, 2-Leads, Body 1.00x0.50mm, IPC Low Density)
pins: 1, 2
1 alternate drawing of the same symbol

## CMP-2002-02445-2
designator R?, comment 1k 0402
RES SMD 1.2K OHM 1% 1/10W 0402; Resistance: 1kR; Tolerance: 0.1%; Max Power Dissipation: 63mW; Temperature Coefficient: 25ppm/°C; MN: MCS04020D1001BE000
footprint FP-MCS0402-IPC_C
footprint FP-MCS0402-IPC_A
footprint FP-MCS0402-MFG
footprint FP-MCS0402-IPC_B
pins: 1, 2

## CMP-2002-02548-2
designator R?, comment 10R 0402
RES SMD 10 OHM 1% 1/16W 0402; Manufacturer Part Number: RT0402FRE0710RL; Manufacturer: Yageo; Resistance: 10Ω; Voltage Rating: 50V; Tolerance: 0.01; Power Rating: 0.063W; Temperature Coefficient: 50 ppm/°C; Value: 10Ω
footprint FP-RT0402-MFG
footprint FP-RT0402-IPC_C
footprint FP-RT0402-IPC_B
footprint FP-RT0402-IPC_A
pins: 1, 2

## CMP-2002-03043-1
designator R?, comment 10KR 0402
CRCW040210K0FKEDHP; Manufacturer: Vishay Dale
footprint RESC1005X40X25ML05T10 (Chip Resistor, 2-Leads, Body 1.00x0.50mm, IPC Low Density)
footprint RESC1005X40X25LL05T10 (Chip Resistor, 2-Leads, Body 1.00x0.50mm, IPC High Density)
footprint RESC1005X40X25NL05T10 (Chip Resistor, 2-Leads, Body 1.00x0.50mm, IPC Medium Density)
pins: 1, 2
1 alternate drawing of the same symbol

## CMP-2002-03111-1
designator R?, comment 20K 0402
Part Number: 8-1879061-0; Manufacturer: TE Connectivity / AMP
footprint RESC1005X35X20ML05T10 (Chip Resistor, 2-Leads, Body 1.00x0.50mm, IPC Low Density)
footprint RESC1005X35X20LL05T10 (Chip Resistor, 2-Leads, Body 1.00x0.50mm, IPC High Density)
footprint RESC1005X35X20NL05T10 (Chip Resistor, 2-Leads, Body 1.00x0.50mm, IPC Medium Density)
pins: 1, 2
1 alternate drawing of the same symbol

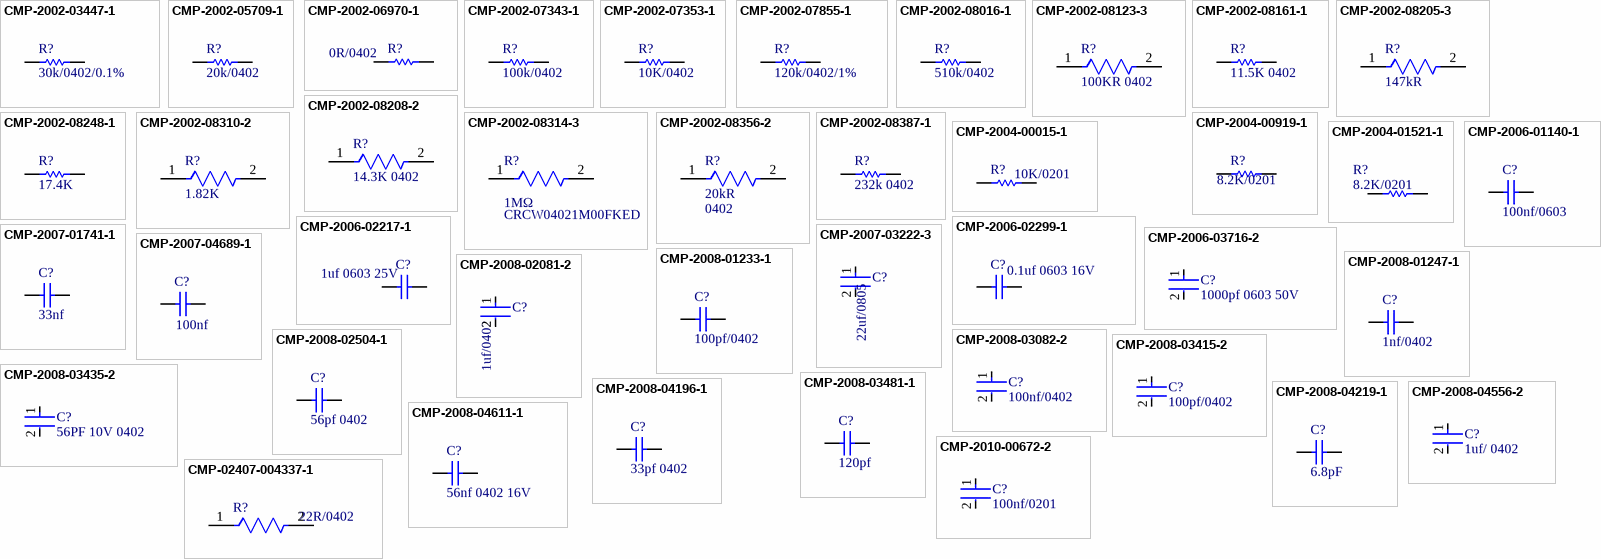
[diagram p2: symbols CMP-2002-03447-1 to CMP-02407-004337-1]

## CMP-2002-03447-1
designator R?, comment 30k/0402/0.1%
Part Number: CPF0402B30KE1; Manufacturer: TE Connectivity / AMP
footprint RESC1005X35X20ML05T10 (Chip Resistor, 2-Leads, Body 1.00x0.50mm, IPC Low Density)
footprint RESC1005X35X20NL05T10 (Chip Resistor, 2-Leads, Body 1.00x0.50mm, IPC Medium Density)
footprint RESC1005X35X20LL05T10 (Chip Resistor, 2-Leads, Body 1.00x0.50mm, IPC High Density)
pins: 1, 2
1 alternate drawing of the same symbol

## CMP-2002-05709-1
designator R?, comment 20k/0402
20k 0402 1%; Manufacturer: TE Connectivity / AMP; Part Number: CRG0402F20K
footprint RESC1005X40X25ML10T10 (Chip Resistor, 2-Leads, Body 1.00x0.50mm, IPC Low Density)
footprint RESC1005X40X25NL10T10 (Chip Resistor, 2-Leads, Body 1.00x0.50mm, IPC Medium Density)
footprint RESC1005X40X25LL10T10 (Chip Resistor, 2-Leads, Body 1.00x0.50mm, IPC High Density)
pins: 1, 2
1 alternate drawing of the same symbol

## CMP-2002-06970-1
designator R?, comment 0R/0402
-55℃~+155℃ 0Ω 62.5mW Thick Film Resistor ±5% 0402 Chip Resistor - Surface Mount ROHS; Part Number: RC0402JR-100RL; Manufacturer: Yageo
footprint RESC1005X40X25NL05T10 (Chip Resistor, 2-Leads, Body 1.00x0.50mm, IPC Medium Density)
footprint RESC1005X40X25LL05T10 (Chip Resistor, 2-Leads, Body 1.00x0.50mm, IPC High Density)
footprint RESC1005X40X25ML05T10 (Chip Resistor, 2-Leads, Body 1.00x0.50mm, IPC Low Density)
pins: 1, 2
1 alternate drawing of the same symbol

## CMP-2002-07343-1
designator R?, comment 100k/0402
Part Number: RC0402FR-07100KL; Manufacturer: Yageo / Phycomp
footprint RESC1005X40X25NL05T10 (Chip Resistor, 2-Leads, Body 1.00x0.50mm, IPC Medium Density)
footprint RESC1005X40X25LL05T10 (Chip Resistor, 2-Leads, Body 1.00x0.50mm, IPC High Density)
footprint RESC1005X40X25ML05T10 (Chip Resistor, 2-Leads, Body 1.00x0.50mm, IPC Low Density)
pins: 1, 2
1 alternate drawing of the same symbol

## CMP-2002-07353-1
designator R?, comment 10K/0402
-55℃~+155℃ 10kΩ 50V 62.5mW Thick Film Resistor ±1% ±100ppm/℃ 0402 Chip Resistor - Surface Mount ROHS; Part Number: RC0402FR-0710KL; Manufacturer: Yageo / Phycomp
footprint RESC1005X40X25LL05T10 (Chip Resistor, 2-Leads, Body 1.00x0.50mm, IPC High Density)
footprint RESC1005X40X25ML05T10 (Chip Resistor, 2-Leads, Body 1.00x0.50mm, IPC Low Density)
footprint RESC1005X40X25NL05T10 (Chip Resistor, 2-Leads, Body 1.00x0.50mm, IPC Medium Density)
pins: 1, 2
1 alternate drawing of the same symbol

## CMP-2002-07855-1
designator R?, comment 120k/0402/1%
Manufacturer: Yageo; Part Number: RC0402FR-13120KL
footprint RESC1005X40X25ML05T10 (Chip Resistor, 2-Leads, Body 1.00x0.50mm, IPC Low Density)
footprint RESC1005X40X25NL05T10 (Chip Resistor, 2-Leads, Body 1.00x0.50mm, IPC Medium Density)
footprint RESC1005X40X25LL05T10 (Chip Resistor, 2-Leads, Body 1.00x0.50mm, IPC High Density)
pins: 1, 2
1 alternate drawing of the same symbol

## CMP-2002-08016-1
designator R?, comment 510k/0402
Part Number: RC0402JR-07510KL; Manufacturer: Yageo
footprint RESC1005X40X25NL05T10 (Chip Resistor, 2-Leads, Body 1.00x0.50mm, IPC Medium Density)
footprint RESC1005X40X25ML05T10 (Chip Resistor, 2-Leads, Body 1.00x0.50mm, IPC Low Density)
footprint RESC1005X40X25LL05T10 (Chip Resistor, 2-Leads, Body 1.00x0.50mm, IPC High Density)
pins: 1, 2
1 alternate drawing of the same symbol

## CMP-2002-08123-3
designator R?, comment 100KR 0402
RES Thick Film, 100kΩ, 1%, 0.063W, 100ppm/°C, 0402; Power Rating: 63mW; Voltage Rating (DC): 50V
footprint FP-CRCW0402-e3-IPC_C
footprint FP-CRCW0402-e3-IPC_A
footprint FP-CRCW0402-e3-IPC_B
footprint FP-CRCW0402-e3-MFG
pins: 1, 2

## CMP-2002-08161-1
designator R?, comment 11.5K 0402
Resistance = 11.5 kΩ / Tolerance = 1.0% / Power = 63 mW / CRCW040211K5FKED; Manufacturer: Vishay Dale
footprint RESC1005X40X25NL05T05 (Chip Resistor, 2-Leads, Body 1.00x0.50mm, IPC Medium Density)
footprint RESC1005X40X25ML05T05 (Chip Resistor, 2-Leads, Body 1.00x0.50mm, IPC Low Density)
footprint RESC1005X40X25LL05T05 (Chip Resistor, 2-Leads, Body 1.00x0.50mm, IPC High Density)
pins: 1, 2
1 alternate drawing of the same symbol

## CMP-2002-08205-3
designator R?, comment Resistance: 147kR  (hidden comment: CRCW0402147KFKED)
RES Thick Film, 147kΩ, 1%, 0.063W, 100ppm/°C, 0402; Voltage Rating: 50V; Power Rating: 63mW
footprint FP-CRCW0402-e3-IPC_A
footprint FP-CRCW0402-e3-IPC_C
footprint FP-CRCW0402-e3-IPC_B
footprint FP-CRCW0402-e3-MFG
pins: 1, 2

## CMP-2002-08208-2
designator R?, comment 14.3K 0402
RES Thick Film, 14.3kΩ, 1%, 0.063W, 100ppm/°C, 0402 / CRCW040214K3FKED; Voltage Rating (DC): 50V; Max Power Dissipation: 63mW; Resistance: 14.3kR
footprint FP-CRCW0402-e3-MFG
footprint FP-CRCW0402-e3-IPC_B
footprint FP-CRCW0402-e3-IPC_A
footprint FP-CRCW0402-e3-IPC_C
pins: 1, 2

## CMP-2002-08248-1
designator R?, comment 17.4K
CRCW040217K4FKED; Manufacturer: Vishay Dale
footprint RESC1005X40X25LL05T05 (Chip Resistor, 2-Leads, Body 1.00x0.50mm, IPC High Density)
footprint RESC1005X40X25ML05T05 (Chip Resistor, 2-Leads, Body 1.00x0.50mm, IPC Low Density)
footprint RESC1005X40X25NL05T05 (Chip Resistor, 2-Leads, Body 1.00x0.50mm, IPC Medium Density)
pins: 1, 2
1 alternate drawing of the same symbol

## CMP-2002-08310-2
designator R?, comment 1.82K
RES Thick Film, 1.82kΩ, 1%, 0.063W, 100ppm/°C, 0402 / CRCW04021K82FKED; Voltage Rating (DC): 50V; Power Rating: 63mW; Tolerance: 5%; Resistance: 1.82kR
footprint FP-CRCW0402-e3-IPC_A
footprint FP-CRCW0402-e3-IPC_B
footprint FP-CRCW0402-e3-MFG
footprint FP-CRCW0402-e3-IPC_C
pins: 1, 2

## CMP-2002-08314-3
designator R?, comment CRCW04021M00FKED
63mW Thick Film Resistors 75V ±1% ±100ppm/℃ 1MΩ 0402 Chip Resistor - Surface Mount ROHS; Voltage Rating: 50V; Temperature Coefficient: 100ppm/°C
footprint CRCW0402-e3_MFG (Recommended Land Pattern)
footprint CRCW0402-e3_L
footprint CRCW0402-e3_M
footprint CRCW0402-e3_N
pins: 1, 2

## CMP-2002-08356-2
designator R?, comment Resistance: 20kR  Case/Package: 0402  (hidden comment: CRCW040220K0FKED)
RES Thick Film, 20kΩ, 1%, 0.063W, 100ppm/°C, 0402; Max Power Dissipation: 63mW; Working Voltage: 50V
footprint FP-CRCW0402-e3-IPC_B
footprint FP-CRCW0402-e3-IPC_A
footprint FP-CRCW0402-e3-IPC_C
footprint FP-CRCW0402-e3-MFG
pins: 1, 2

## CMP-2002-08387-1
designator R?, comment 232k 0402
Part Number: CRCW0402232KFKED; Manufacturer: Vishay Dale
footprint RESC1005X40X25ML05T05 (Chip Resistor, 2-Leads, Body 1.00x0.50mm, IPC Low Density)
footprint RESC1005X40X25LL05T05 (Chip Resistor, 2-Leads, Body 1.00x0.50mm, IPC High Density)
footprint RESC1005X40X25NL05T05 (Chip Resistor, 2-Leads, Body 1.00x0.50mm, IPC Medium Density)
pins: 1, 2
1 alternate drawing of the same symbol

## CMP-2004-00015-1
designator R?, comment 10K/0201
Part Number: CRCW020110K0FKED; Manufacturer: Vishay Dale
footprint RESC0603X28X15LL05T05 (Chip Resistor, 2-Leads, Body 0.60x0.30mm, IPC High Density)
footprint RESC0603X28X15ML05T05 (Chip Resistor, 2-Leads, Body 0.60x0.30mm, IPC Low Density)
footprint RESC0603X28X15NL05T05 (Chip Resistor, 2-Leads, Body 0.60x0.30mm, IPC Medium Density)
pins: 1, 2
1 alternate drawing of the same symbol

## CMP-2004-00919-1
designator R?, comment 8.2K/0201
Manufacturer: Vishay Dale; Part Number: CRCW02018K20FKED
footprint RESC0603X28X15NL05T05 (Chip Resistor, 2-Leads, Body 0.60x0.30mm, IPC Medium Density)
footprint RESC0603X28X15LL05T05 (Chip Resistor, 2-Leads, Body 0.60x0.30mm, IPC High Density)
footprint RESC0603X28X15ML05T05 (Chip Resistor, 2-Leads, Body 0.60x0.30mm, IPC Low Density)
pins: 1, 2
1 alternate drawing of the same symbol

## CMP-2004-01521-1
designator R?, comment 8.2K/0201
Manufacturer: KOA Speer; Part Number: RK73H1HTTC8201F
footprint RESC0603X26X15ML03T05 (Chip Resistor, 2-Leads, Body 0.60x0.30mm, IPC Low Density)
footprint RESC0603X26X15NL03T05 (Chip Resistor, 2-Leads, Body 0.60x0.30mm, IPC Medium Density)
footprint RESC0603X26X15LL03T05 (Chip Resistor, 2-Leads, Body 0.60x0.30mm, IPC High Density)
pins: 1, 2
1 alternate drawing of the same symbol

## CMP-2006-01140-1
designator C?, comment 100nf/0603
Part Number: VJ0603Y104MXXAC; Manufacturer: Vitramon
footprint CAPC1608X92X38ML15T08 (Chip Capacitor, 2-Leads, Body 1.60x0.80mm, IPC Low Density)
footprint CAPC1608X92X38LL15T08 (Chip Capacitor, 2-Leads, Body 1.60x0.80mm, IPC High Density)
footprint CAPC1608X92X38NL15T08 (Chip Capacitor, 2-Leads, Body 1.60x0.80mm, IPC Medium Density)
pins: 1, 2
1 alternate drawing of the same symbol

## CMP-2006-02217-1
designator C?, comment 1uf 0603 25V
Part Number: C0603C105M3RACTU; Manufacturer: Kemet
footprint CAPC1608X95X35NL15T15 (Chip Capacitor, 2-Leads, Body 1.60x0.80mm, IPC Medium Density)
footprint CAPC1608X95X35ML15T15 (Chip Capacitor, 2-Leads, Body 1.60x0.80mm, IPC Low Density)
footprint CAPC1608X95X35LL15T15 (Chip Capacitor, 2-Leads, Body 1.60x0.80mm, IPC High Density)
pins: 1, 2
1 alternate drawing of the same symbol

## CMP-2006-02299-1
designator C?, comment 0.1uf 0603 16V
Part Number: C0603C104K4RAC7013; Manufacturer: Kemet
footprint CAPC1608X90X35NL15T15 (Chip Capacitor, 2-Leads, Body 1.60x0.81mm, IPC Medium Density)
footprint CAPC1608X90X35LL15T15 (Chip Capacitor, 2-Leads, Body 1.60x0.81mm, IPC High Density)
footprint CAPC1608X90X35ML15T15 (Chip Capacitor, 2-Leads, Body 1.60x0.81mm, IPC Low Density)
pins: 1, 2
1 alternate drawing of the same symbol

## CMP-2006-03716-2
designator C?, comment 1000pf 0603 50V
CAP CER 1000PF 50V X7R 0603; Manufacturer Part Number: C0603C102K5RACAUTO; Manufacturer: KEMET; Material: Ceramic; Automotive Grade: Grade 1; Value: 1,000 pF; Tolerance: 0.1; Temperature Coefficient: 30ppm/°C
footprint FP-C0603C-CF-MFG
footprint FP-C0603C-CF-IPC_C
footprint FP-C0603C-CF-IPC_B
footprint FP-C0603C-CF-IPC_A
pins: 1, 2

## CMP-2007-01741-1
designator C?, comment 33nf
VJ-0805Y333KXBMT; Manufacturer: Vitramon
footprint CAPC2013X145X48NL20T23 (Chip Capacitor, 2-Leads, Body 2.00x1.25mm, IPC Medium Density)
footprint CAPC2013X145X48ML20T23 (Chip Capacitor, 2-Leads, Body 2.00x1.25mm, IPC Low Density)
footprint CAPC2013X145X48LL20T23 (Chip Capacitor, 2-Leads, Body 2.00x1.25mm, IPC High Density)
pins: 1, 2
1 alternate drawing of the same symbol

## CMP-2007-03222-3
designator C?, comment 22uf/0805
22uF 25V X5R ±20% 0805 Multilayer Ceramic Capacitors MLCC - SMD/SMT ROHS
footprint FP-GRM21B-0_2-e0_2_0_7-IPC_B
footprint FP-GRM21B-0_2-e0_2_0_7-MFG
footprint FP-GRM21B-0_2-e0_2_0_7-IPC_C
footprint FP-GRM21B-0_2-e0_2_0_7-IPC_A
pins: 1, 2

## CMP-2007-04689-1
designator C?, comment value 100nf  (hidden comment: 08055D104KAT2A)
Manufacturer: AVX Interconnect / Elco
footprint CAPC2013X140X50ML20T25 (Chip Capacitor, 2-Leads, Body 2.00x1.25mm, IPC Low Density)
footprint CAPC2013X140X50NL20T25 (Chip Capacitor, 2-Leads, Body 2.00x1.25mm, IPC Medium Density)
footprint CAPC2013X140X50LL20T25 (Chip Capacitor, 2-Leads, Body 2.00x1.25mm, IPC High Density)
pins: 1, 2
1 alternate drawing of the same symbol

## CMP-2008-01233-1
designator C?, comment 100pf/0402
Part Number: VJ0402Y101KXAPW1BC; Manufacturer: Vitramon
footprint CAPC1005X55X25ML05T05 (Chip Capacitor, 2-Leads, Body 1.00x0.50mm, IPC Low Density)
footprint CAPC1005X55X25NL05T05 (Chip Capacitor, 2-Leads, Body 1.00x0.50mm, IPC Medium Density)
footprint CAPC1005X55X25LL05T05 (Chip Capacitor, 2-Leads, Body 1.00x0.50mm, IPC High Density)
pins: 1, 2
1 alternate drawing of the same symbol

## CMP-2008-01247-1
designator C?, comment 1nf/0402
Manufacturer: Vitramon; Part Number: VJ0402Y102KXXPW1BC
footprint CAPC1005X55X25LL05T05 (Chip Capacitor, 2-Leads, Body 1.00x0.50mm, IPC High Density)
footprint CAPC1005X55X25ML05T05 (Chip Capacitor, 2-Leads, Body 1.00x0.50mm, IPC Low Density)
footprint CAPC1005X55X25NL05T05 (Chip Capacitor, 2-Leads, Body 1.00x0.50mm, IPC Medium Density)
pins: 1, 2
1 alternate drawing of the same symbol

## CMP-2008-02081-2
designator C?, comment 1uf/0402
CAP CER 1UF 10V X5R 0402; Dielectric Material: Ceramic; Dissipation Factor: 5%; Tolerance: 10%
footprint FP-C0402C105K8PACTU-MFG
footprint FP-C0402C105K8PACTU-IPC_C
footprint FP-C0402C105K8PACTU-IPC_B
footprint FP-C0402C105K8PACTU-IPC_A
pins: 1, 2

## CMP-2008-02504-1
designator C?, comment 56pf 0402
04023A560KAT2A; Manufacturer: AVX Interconnect / Elco
footprint CAPC1005X56X25LL10T15 (Chip Capacitor, 2-Leads, Body 1.00x0.50mm, IPC High Density)
footprint CAPC1005X56X25ML10T15 (Chip Capacitor, 2-Leads, Body 1.00x0.50mm, IPC Low Density)
footprint CAPC1005X56X25NL10T15 (Chip Capacitor, 2-Leads, Body 1.00x0.50mm, IPC Medium Density)
pins: 1, 2
1 alternate drawing of the same symbol

## CMP-2008-03082-2
designator C?, comment 100nf/0402
CAP CER 0.1UF 16V X7R 0402; Manufacturer Part Number: C0402C104K4RACAUTO; Manufacturer: Kemet; Temperature Coefficient: 15%; Tolerance: 0.1; Capacitance: 0.10 μF; Material: Ceramic; Value: 0.10 μF
footprint FP-C0402-BB-MFG
footprint FP-C0402-BB-IPC_C
footprint FP-C0402-BB-IPC_B
footprint FP-C0402-BB-IPC_A
pins: 1, 2

## CMP-2008-03415-2
designator C?, comment 100pf/0402
Cap Ceramic 100pF 50V C0G 5% Pad SMD 0402 125C Automotive T/R; Manufacturer Part Number: C0402C101J5GACAUTO; Manufacturer: Kemet; Temperature Coefficient: 15%; Tolerance: 0.05
footprint FP-C0402-BB-MFG
footprint FP-C0402-BB-IPC_C
footprint FP-C0402-BB-IPC_B
footprint FP-C0402-BB-IPC_A
pins: 1, 2

## CMP-2008-03435-2
designator C?, comment 56PF 10V 0402
CAP CER 56PF 10V NP0 0402 / C0402C560J8GACTU; Manufacturer: Kemet; Material: Ceramic; Tolerance: 0.05; Temperature Characteristic: C0G; Temperature Coefficient: 15%
footprint FP-C0402-BB-MFG
footprint FP-C0402-BB-IPC_C
footprint FP-C0402-BB-IPC_B
footprint FP-C0402-BB-IPC_A
pins: 1, 2

## CMP-2008-03481-1
designator C?, comment 120pf
C0402C121G5GACTU; Manufacturer: Kemet
footprint CAPC1005X55X30ML05T10 (Chip Capacitor, 2-Leads, Body 1.00x0.50mm, IPC Low Density)
footprint CAPC1005X55X30NL05T10 (Chip Capacitor, 2-Leads, Body 1.00x0.50mm, IPC Medium Density)
footprint CAPC1005X55X30LL05T10 (Chip Capacitor, 2-Leads, Body 1.00x0.50mm, IPC High Density)
pins: 1, 2
1 alternate drawing of the same symbol

## CMP-2008-04196-1
designator C?, comment 33pf 0402
GRM1555C1E330JA01D; Manufacturer: Murata
footprint CAPC1005X55X25ML05T10 (Chip Capacitor, 2-Leads, Body 1.00x0.50mm, IPC Low Density)
footprint CAPC1005X55X25NL05T10 (Chip Capacitor, 2-Leads, Body 1.00x0.50mm, IPC Medium Density)
footprint CAPC1005X55X25LL05T10 (Chip Capacitor, 2-Leads, Body 1.00x0.50mm, IPC High Density)
pins: 1, 2
1 alternate drawing of the same symbol

## CMP-2008-04219-1
designator C?, comment value 6.8pF  (hidden comment: GRM1555C1E6R8CA01D)
Manufacturer: Murata
footprint CAPC1005X55X25NL05T10 (Chip Capacitor, 2-Leads, Body 1.00x0.50mm, IPC Medium Density)
footprint CAPC1005X55X25ML05T10 (Chip Capacitor, 2-Leads, Body 1.00x0.50mm, IPC Low Density)
footprint CAPC1005X55X25LL05T10 (Chip Capacitor, 2-Leads, Body 1.00x0.50mm, IPC High Density)
pins: 1, 2
1 alternate drawing of the same symbol

## CMP-2008-04556-2
designator C?, comment 1uf/ 0402
CAP CER 1UF 10V X5R 0402; Manufacturer Part Number: GRM155R61A105KE15D; Manufacturer: Murata; Material: Ceramic; Tolerance: 10%; Temperature Coefficient: 15%
footprint FP-GRM15-0_1-MFG
footprint FP-GRM15-0_1-IPC_C
footprint FP-GRM15-0_1-IPC_B
footprint FP-GRM15-0_1-IPC_A
pins: 1, 2

## CMP-2008-04611-1
designator C?, comment 56nf 0402 16V
GRM155R71C563KA88D; Manufacturer: Murata
footprint CAPC1005X55X25ML05T10 (Chip Capacitor, 2-Leads, Body 1.00x0.50mm, IPC Low Density)
footprint CAPC1005X55X25NL05T10 (Chip Capacitor, 2-Leads, Body 1.00x0.50mm, IPC Medium Density)
footprint CAPC1005X55X25LL05T10 (Chip Capacitor, 2-Leads, Body 1.00x0.50mm, IPC High Density)
pins: 1, 2
1 alternate drawing of the same symbol

## CMP-2010-00672-2
designator C?, comment 100nf/0201
Cap Ceramic 100nF 10V X5R ±10% Pad SMD 0201 +85°C T/R; MN: CL03A104KP3NNNC
footprint FP-CL03-IPC_C
footprint FP-CL03-IPC_A
footprint FP-CL03-IPC_B
pins: 1, 2

## CMP-02407-004337-1
designator R?, comment 22R/0402
RES Thick Film, 22Ω, 1%, 0.063W, 100ppm/°C, 0402; Resistance: 22R; Max Power Dissipation: 63mW
footprint FP-CRCW0402-e3-IPC_C
footprint FP-CRCW0402-e3-IPC_A
footprint FP-CRCW0402-e3-MFG
footprint FP-CRCW0402-e3-IPC_B
pins: 1, 2

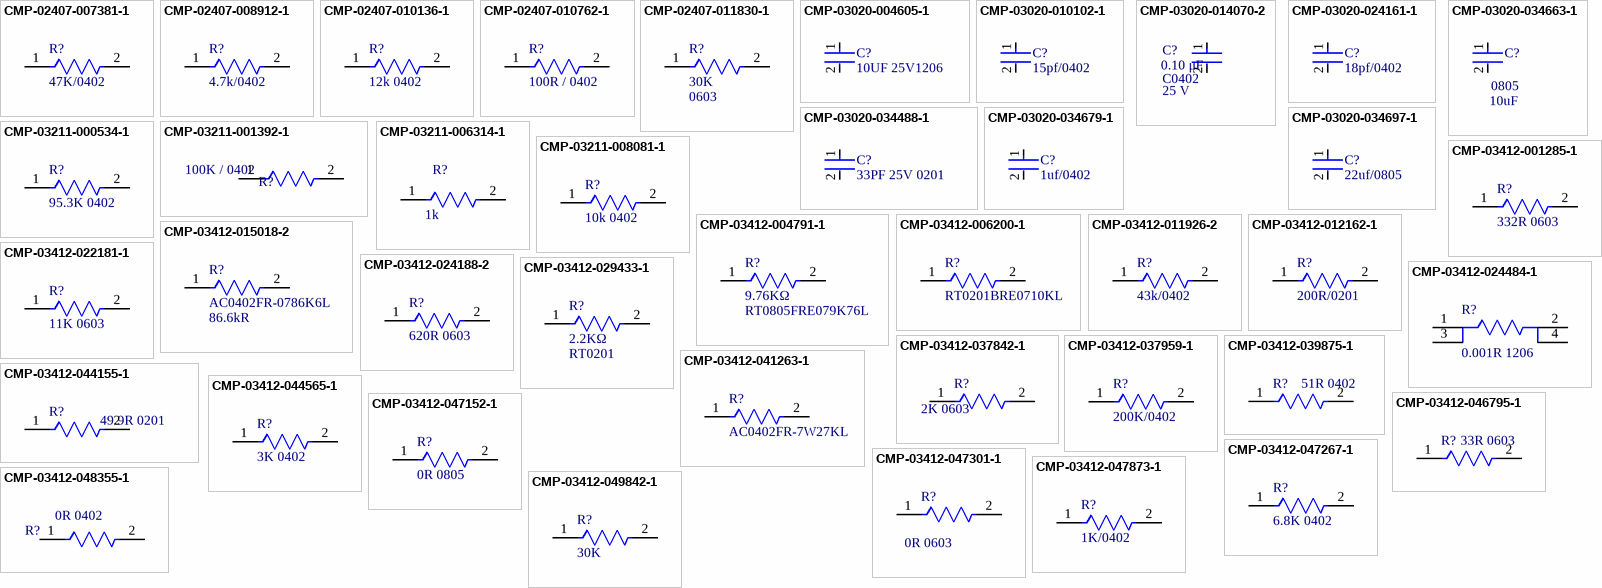
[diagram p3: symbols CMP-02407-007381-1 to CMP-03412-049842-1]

## CMP-02407-007381-1
designator R?, comment 47K/0402
RES Thick Film, 47kΩ, 1%, 0.063W, 100ppm/°C, 0402; Max Power Dissipation: 63mW; Resistance: 47kR
footprint FP-CRCW0402-e3-IPC_B
footprint FP-CRCW0402-e3-MFG
footprint FP-CRCW0402-e3-IPC_C
footprint FP-CRCW0402-e3-IPC_A
pins: 1, 2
